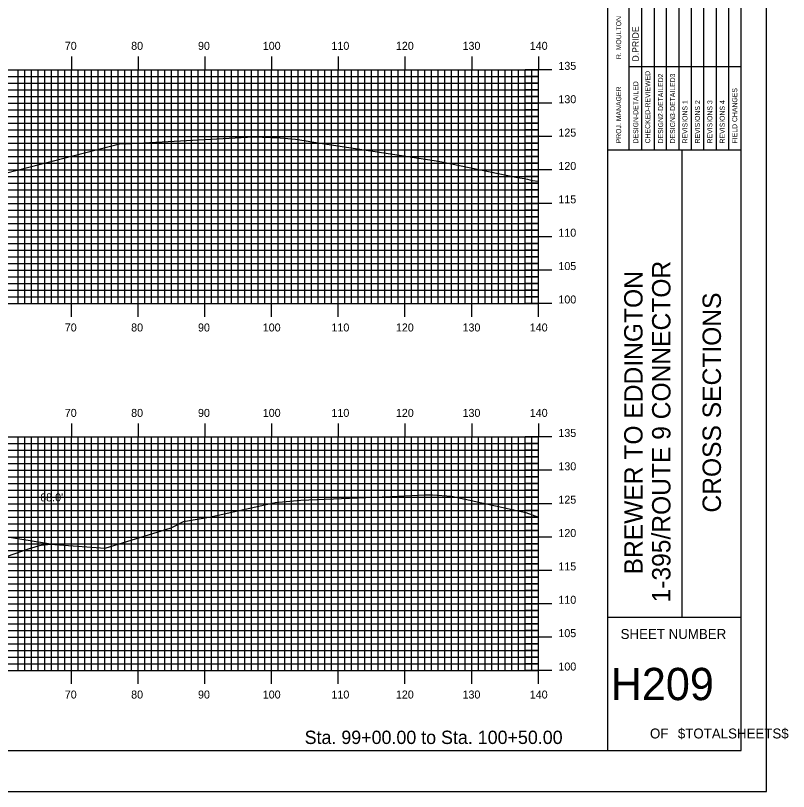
# Model space of a CAD drawing. Extents: x 1766513 to 1766856, y 442591 to 442811.
# Drawn here: x 1766740.5 to 1766856.4, y 442590.5 to 442706.8 of the extents above; entities that cross this region are included whole.
import ezdxf

# ---------------------------------------------------------------- set-up
doc = ezdxf.new("R2010")
doc.units = 0
for name, color, linetype in [('BORDER', 7, 'Continuous'), ('D_Roadway_Centerline', 7, 'Continuous'), ('D_Text_Standard', 7, 'Continuous'), ('H_V ANNOTATION', 7, 'Continuous'), ('MAJOR', 7, 'Continuous'), ('MINOR', 7, 'Continuous'), ('PLOT BOUNDARY', 7, 'Continuous'), ('S_Roadway_Centerline', 7, 'Continuous')]:
    doc.layers.add(name, color=color, linetype=linetype)

msp = doc.modelspace()

# ---------------------------------------------------------------- linework, layer by layer
at = {"layer": 'BORDER'}
for p, q in [((1766829.31, 442596.67), (1766829.31, 442806.67)), ((1766829.31, 442686.67), (1766849.31, 442686.67)), ((1766840.49, 442616.67), (1766840.49, 442686.67)), ((1766829.31, 442616.67), (1766849.31, 442616.67))]:
    msp.add_line(p, q, dxfattribs=at)
msp.add_lwpolyline([(1766529.31, 442596.67), (1766849.31, 442596.67), (1766849.31, 442806.67), (1766529.31, 442806.67)], close=True, dxfattribs=at)
for points in [[(1766834.41, 442686.68), (1766834.41, 442721.67)], [(1766836.27, 442721.67), (1766836.27, 442686.68)], [(1766838.13, 442686.68), (1766838.13, 442721.67)], [(1766840, 442686.68), (1766840, 442721.67)], [(1766841.86, 442686.68), (1766841.86, 442721.67)], [(1766843.72, 442686.68), (1766843.72, 442721.67)], [(1766845.59, 442686.68), (1766845.59, 442721.67)], [(1766847.45, 442686.68), (1766847.45, 442721.67)], [(1766832.54, 442686.68), (1766832.54, 442720.26)], [(1766832.54, 442699.17), (1766849.31, 442699.17)]]:
    msp.add_lwpolyline(points, dxfattribs=at)
at = {"layer": 'D_Roadway_Centerline'}
msp.add_line((1766713.08, 442617.08), (1766742.93, 442627.03), dxfattribs=at)
msp.add_arc((1766746.1, 442617.54), 10, 85.9694, 108.438, dxfattribs=at)
at = {"layer": 'MAJOR'}
for p, q in [((1766748.91, 442700.67), (1766748.91, 442698.67)), ((1766758.91, 442700.67), (1766758.91, 442698.67)), ((1766768.91, 442700.67), (1766768.91, 442698.67)), ((1766778.91, 442700.67), (1766778.91, 442698.67)), ((1766788.91, 442700.67), (1766788.91, 442698.67)), ((1766798.91, 442700.67), (1766798.91, 442698.67)), ((1766808.91, 442700.67), (1766808.91, 442698.67)), ((1766818.91, 442700.67), (1766818.91, 442698.67)), ((1766538.91, 442698.67), (1766818.91, 442698.67)), ((1766538.91, 442698.67), (1766818.91, 442698.67)), ((1766748.91, 442663.67), (1766748.91, 442698.67)), ((1766758.91, 442663.67), (1766758.91, 442698.67)), ((1766768.91, 442663.67), (1766768.91, 442698.67)), ((1766778.91, 442663.67), (1766778.91, 442698.67)), ((1766788.91, 442663.67), (1766788.91, 442698.67)), ((1766798.91, 442663.67), (1766798.91, 442698.67)), ((1766808.91, 442663.67), (1766808.91, 442698.67)), ((1766820.91, 442698.67), (1766816.91, 442698.67)), ((1766818.91, 442663.67), (1766818.91, 442698.67)), ((1766818.91, 442663.67), (1766818.91, 442698.67)), ((1766538.91, 442693.67), (1766818.91, 442693.67)), ((1766820.91, 442693.67), (1766816.91, 442693.67)), ((1766538.91, 442688.67), (1766818.91, 442688.67)), ((1766820.91, 442688.67), (1766816.91, 442688.67)), ((1766538.91, 442683.67), (1766818.91, 442683.67)), ((1766820.91, 442683.67), (1766816.91, 442683.67)), ((1766538.91, 442678.67), (1766818.91, 442678.67)), ((1766820.91, 442678.67), (1766816.91, 442678.67)), ((1766538.91, 442673.67), (1766818.91, 442673.67)), ((1766820.91, 442673.67), (1766816.91, 442673.67)), ((1766538.91, 442668.67), (1766818.91, 442668.67)), ((1766820.91, 442668.67), (1766816.91, 442668.67)), ((1766538.91, 442663.67), (1766818.91, 442663.67)), ((1766538.91, 442663.67), (1766818.91, 442663.67)), ((1766748.91, 442661.66), (1766748.91, 442663.67)), ((1766758.91, 442661.66), (1766758.91, 442663.67)), ((1766768.91, 442661.66), (1766768.91, 442663.67)), ((1766778.91, 442661.66), (1766778.91, 442663.67)), ((1766788.91, 442661.66), (1766788.91, 442663.67)), ((1766798.91, 442661.66), (1766798.91, 442663.67)), ((1766808.91, 442661.66), (1766808.91, 442663.67)), ((1766820.91, 442663.67), (1766816.91, 442663.67)), ((1766818.91, 442661.66), (1766818.91, 442663.67)), ((1766748.91, 442645.67), (1766748.91, 442643.67)), ((1766758.91, 442645.67), (1766758.91, 442643.67)), ((1766768.91, 442645.67), (1766768.91, 442643.67)), ((1766778.91, 442645.67), (1766778.91, 442643.67)), ((1766788.91, 442645.67), (1766788.91, 442643.67)), ((1766798.91, 442645.67), (1766798.91, 442643.67)), ((1766808.91, 442645.67), (1766808.91, 442643.67)), ((1766818.91, 442645.67), (1766818.91, 442643.67)), ((1766538.91, 442643.67), (1766818.91, 442643.67)), ((1766538.91, 442643.67), (1766818.91, 442643.67)), ((1766748.91, 442608.67), (1766748.91, 442643.67)), ((1766758.91, 442608.67), (1766758.91, 442643.67)), ((1766768.91, 442608.67), (1766768.91, 442643.67)), ((1766778.91, 442608.67), (1766778.91, 442643.67)), ((1766788.91, 442608.67), (1766788.91, 442643.67)), ((1766798.91, 442608.67), (1766798.91, 442643.67)), ((1766808.91, 442608.67), (1766808.91, 442643.67)), ((1766820.91, 442643.67), (1766816.91, 442643.67)), ((1766818.91, 442608.67), (1766818.91, 442643.67)), ((1766818.91, 442608.67), (1766818.91, 442643.67)), ((1766538.91, 442638.67), (1766818.91, 442638.67)), ((1766820.91, 442638.67), (1766816.91, 442638.67)), ((1766538.91, 442633.67), (1766818.91, 442633.67)), ((1766820.91, 442633.67), (1766816.91, 442633.67)), ((1766538.91, 442628.67), (1766818.91, 442628.67)), ((1766820.91, 442628.67), (1766816.91, 442628.67)), ((1766538.91, 442623.67), (1766818.91, 442623.67)), ((1766820.91, 442623.67), (1766816.91, 442623.67)), ((1766538.91, 442618.67), (1766818.91, 442618.67)), ((1766820.91, 442618.67), (1766816.91, 442618.67)), ((1766538.91, 442613.67), (1766818.91, 442613.67)), ((1766820.91, 442613.67), (1766816.91, 442613.67)), ((1766538.91, 442608.67), (1766818.91, 442608.67)), ((1766538.91, 442608.67), (1766818.91, 442608.67)), ((1766748.91, 442606.66), (1766748.91, 442608.67)), ((1766758.91, 442606.66), (1766758.91, 442608.67)), ((1766768.91, 442606.66), (1766768.91, 442608.67)), ((1766778.91, 442606.66), (1766778.91, 442608.67)), ((1766788.91, 442606.66), (1766788.91, 442608.67)), ((1766798.91, 442606.66), (1766798.91, 442608.67)), ((1766808.91, 442606.66), (1766808.91, 442608.67)), ((1766820.91, 442608.67), (1766816.91, 442608.67)), ((1766818.91, 442606.66), (1766818.91, 442608.67))]:
    msp.add_line(p, q, dxfattribs=at)
at = {"layer": 'MINOR'}
for p, q in [((1766740.91, 442663.67), (1766740.91, 442698.67)), ((1766741.91, 442663.67), (1766741.91, 442698.67)), ((1766742.91, 442663.67), (1766742.91, 442698.67)), ((1766743.91, 442663.67), (1766743.91, 442698.67)), ((1766744.91, 442663.67), (1766744.91, 442698.67)), ((1766745.91, 442663.67), (1766745.91, 442698.67)), ((1766746.91, 442663.67), (1766746.91, 442698.67)), ((1766747.91, 442663.67), (1766747.91, 442698.67)), ((1766749.91, 442663.67), (1766749.91, 442698.67)), ((1766750.91, 442663.67), (1766750.91, 442698.67)), ((1766751.91, 442663.67), (1766751.91, 442698.67)), ((1766752.91, 442663.67), (1766752.91, 442698.67)), ((1766753.91, 442663.67), (1766753.91, 442698.67)), ((1766754.91, 442663.67), (1766754.91, 442698.67)), ((1766755.91, 442663.67), (1766755.91, 442698.67)), ((1766756.91, 442663.67), (1766756.91, 442698.67)), ((1766757.91, 442663.67), (1766757.91, 442698.67)), ((1766759.91, 442663.67), (1766759.91, 442698.67)), ((1766760.91, 442663.67), (1766760.91, 442698.67)), ((1766761.91, 442663.67), (1766761.91, 442698.67)), ((1766762.91, 442663.67), (1766762.91, 442698.67)), ((1766763.91, 442663.67), (1766763.91, 442698.67)), ((1766764.91, 442663.67), (1766764.91, 442698.67)), ((1766765.91, 442663.67), (1766765.91, 442698.67)), ((1766766.91, 442663.67), (1766766.91, 442698.67)), ((1766767.91, 442663.67), (1766767.91, 442698.67)), ((1766769.91, 442663.67), (1766769.91, 442698.67)), ((1766770.91, 442663.67), (1766770.91, 442698.67)), ((1766771.91, 442663.67), (1766771.91, 442698.67)), ((1766772.91, 442663.67), (1766772.91, 442698.67)), ((1766773.91, 442663.67), (1766773.91, 442698.67)), ((1766774.91, 442663.67), (1766774.91, 442698.67)), ((1766775.91, 442663.67), (1766775.91, 442698.67)), ((1766776.91, 442663.67), (1766776.91, 442698.67)), ((1766777.91, 442663.67), (1766777.91, 442698.67)), ((1766779.91, 442663.67), (1766779.91, 442698.67)), ((1766780.91, 442663.67), (1766780.91, 442698.67)), ((1766781.91, 442663.67), (1766781.91, 442698.67)), ((1766782.91, 442663.67), (1766782.91, 442698.67)), ((1766783.91, 442663.67), (1766783.91, 442698.67)), ((1766784.91, 442663.67), (1766784.91, 442698.67)), ((1766785.91, 442663.67), (1766785.91, 442698.67)), ((1766786.91, 442663.67), (1766786.91, 442698.67)), ((1766787.91, 442663.67), (1766787.91, 442698.67)), ((1766789.91, 442663.67), (1766789.91, 442698.67)), ((1766790.91, 442663.67), (1766790.91, 442698.67)), ((1766791.91, 442663.67), (1766791.91, 442698.67)), ((1766792.91, 442663.67), (1766792.91, 442698.67)), ((1766793.91, 442663.67), (1766793.91, 442698.67)), ((1766794.91, 442663.67), (1766794.91, 442698.67)), ((1766795.91, 442663.67), (1766795.91, 442698.67)), ((1766796.91, 442663.67), (1766796.91, 442698.67)), ((1766797.91, 442663.67), (1766797.91, 442698.67)), ((1766799.91, 442663.67), (1766799.91, 442698.67)), ((1766800.91, 442663.67), (1766800.91, 442698.67)), ((1766801.91, 442663.67), (1766801.91, 442698.67)), ((1766802.91, 442663.67), (1766802.91, 442698.67)), ((1766803.91, 442663.67), (1766803.91, 442698.67)), ((1766804.91, 442663.67), (1766804.91, 442698.67)), ((1766805.91, 442663.67), (1766805.91, 442698.67)), ((1766806.91, 442663.67), (1766806.91, 442698.67)), ((1766807.91, 442663.67), (1766807.91, 442698.67)), ((1766809.91, 442663.67), (1766809.91, 442698.67)), ((1766810.91, 442663.67), (1766810.91, 442698.67)), ((1766811.91, 442663.67), (1766811.91, 442698.67)), ((1766812.91, 442663.67), (1766812.91, 442698.67)), ((1766813.91, 442663.67), (1766813.91, 442698.67)), ((1766814.91, 442663.67), (1766814.91, 442698.67)), ((1766815.91, 442663.67), (1766815.91, 442698.67)), ((1766816.91, 442663.67), (1766816.91, 442698.67)), ((1766817.91, 442663.67), (1766817.91, 442698.67)), ((1766538.91, 442697.67), (1766818.91, 442697.67)), ((1766818.91, 442697.67), (1766816.91, 442697.67)), ((1766538.91, 442696.67), (1766818.91, 442696.67)), ((1766818.91, 442696.67), (1766816.91, 442696.67)), ((1766538.91, 442695.67), (1766818.91, 442695.67)), ((1766818.91, 442695.67), (1766816.91, 442695.67)), ((1766538.91, 442694.67), (1766818.91, 442694.67)), ((1766818.91, 442694.67), (1766816.91, 442694.67)), ((1766538.91, 442692.67), (1766818.91, 442692.67)), ((1766538.91, 442691.67), (1766818.91, 442691.67)), ((1766818.91, 442692.67), (1766816.91, 442692.67)), ((1766818.91, 442691.67), (1766816.91, 442691.67)), ((1766538.91, 442690.67), (1766818.91, 442690.67)), ((1766818.91, 442690.67), (1766816.91, 442690.67)), ((1766538.91, 442689.67), (1766818.91, 442689.67)), ((1766818.91, 442689.67), (1766816.91, 442689.67)), ((1766538.91, 442687.67), (1766818.91, 442687.67)), ((1766818.91, 442687.67), (1766816.91, 442687.67)), ((1766538.91, 442686.67), (1766818.91, 442686.67)), ((1766818.91, 442686.67), (1766816.91, 442686.67)), ((1766538.91, 442685.67), (1766818.91, 442685.67)), ((1766538.91, 442684.67), (1766818.91, 442684.67)), ((1766818.91, 442685.67), (1766816.91, 442685.67)), ((1766818.91, 442684.67), (1766816.91, 442684.67)), ((1766538.91, 442682.67), (1766818.91, 442682.67)), ((1766818.91, 442682.67), (1766816.91, 442682.67)), ((1766538.91, 442681.67), (1766818.91, 442681.67)), ((1766818.91, 442681.67), (1766816.91, 442681.67)), ((1766538.91, 442680.67), (1766818.91, 442680.67)), ((1766818.91, 442680.67), (1766816.91, 442680.67)), ((1766538.91, 442679.67), (1766818.91, 442679.67)), ((1766818.91, 442679.67), (1766816.91, 442679.67)), ((1766538.91, 442677.67), (1766818.91, 442677.67)), ((1766538.91, 442676.67), (1766818.91, 442676.67)), ((1766818.91, 442677.67), (1766816.91, 442677.67)), ((1766818.91, 442676.67), (1766816.91, 442676.67)), ((1766538.91, 442675.67), (1766818.91, 442675.67)), ((1766818.91, 442675.67), (1766816.91, 442675.67)), ((1766538.91, 442674.67), (1766818.91, 442674.67)), ((1766818.91, 442674.67), (1766816.91, 442674.67)), ((1766538.91, 442672.67), (1766818.91, 442672.67)), ((1766818.91, 442672.67), (1766816.91, 442672.67)), ((1766538.91, 442671.67), (1766818.91, 442671.67)), ((1766818.91, 442671.67), (1766816.91, 442671.67)), ((1766538.91, 442670.67), (1766818.91, 442670.67)), ((1766538.91, 442669.67), (1766818.91, 442669.67)), ((1766818.91, 442670.67), (1766816.91, 442670.67)), ((1766818.91, 442669.67), (1766816.91, 442669.67)), ((1766538.91, 442667.67), (1766818.91, 442667.67)), ((1766818.91, 442667.67), (1766816.91, 442667.67)), ((1766538.91, 442666.67), (1766818.91, 442666.67)), ((1766818.91, 442666.67), (1766816.91, 442666.67)), ((1766538.91, 442665.67), (1766818.91, 442665.67)), ((1766818.91, 442665.67), (1766816.91, 442665.67)), ((1766538.91, 442664.67), (1766818.91, 442664.67)), ((1766818.91, 442664.67), (1766816.91, 442664.67)), ((1766740.91, 442608.67), (1766740.91, 442643.67)), ((1766741.91, 442608.67), (1766741.91, 442643.67)), ((1766742.91, 442608.67), (1766742.91, 442643.67)), ((1766743.91, 442608.67), (1766743.91, 442643.67)), ((1766744.91, 442608.67), (1766744.91, 442643.67)), ((1766745.91, 442608.67), (1766745.91, 442643.67)), ((1766746.91, 442608.67), (1766746.91, 442643.67)), ((1766747.91, 442608.67), (1766747.91, 442643.67)), ((1766749.91, 442608.67), (1766749.91, 442643.67)), ((1766750.91, 442608.67), (1766750.91, 442643.67)), ((1766751.91, 442608.67), (1766751.91, 442643.67)), ((1766752.91, 442608.67), (1766752.91, 442643.67)), ((1766753.91, 442608.67), (1766753.91, 442643.67)), ((1766754.91, 442608.67), (1766754.91, 442643.67)), ((1766755.91, 442608.67), (1766755.91, 442643.67)), ((1766756.91, 442608.67), (1766756.91, 442643.67)), ((1766757.91, 442608.67), (1766757.91, 442643.67)), ((1766759.91, 442608.67), (1766759.91, 442643.67)), ((1766760.91, 442608.67), (1766760.91, 442643.67)), ((1766761.91, 442608.67), (1766761.91, 442643.67)), ((1766762.91, 442608.67), (1766762.91, 442643.67)), ((1766763.91, 442608.67), (1766763.91, 442643.67)), ((1766764.91, 442608.67), (1766764.91, 442643.67)), ((1766765.91, 442608.67), (1766765.91, 442643.67)), ((1766766.91, 442608.67), (1766766.91, 442643.67)), ((1766767.91, 442608.67), (1766767.91, 442643.67)), ((1766769.91, 442608.67), (1766769.91, 442643.67)), ((1766770.91, 442608.67), (1766770.91, 442643.67)), ((1766771.91, 442608.67), (1766771.91, 442643.67)), ((1766772.91, 442608.67), (1766772.91, 442643.67)), ((1766773.91, 442608.67), (1766773.91, 442643.67)), ((1766774.91, 442608.67), (1766774.91, 442643.67)), ((1766775.91, 442608.67), (1766775.91, 442643.67)), ((1766776.91, 442608.67), (1766776.91, 442643.67)), ((1766777.91, 442608.67), (1766777.91, 442643.67)), ((1766779.91, 442608.67), (1766779.91, 442643.67)), ((1766780.91, 442608.67), (1766780.91, 442643.67)), ((1766781.91, 442608.67), (1766781.91, 442643.67)), ((1766782.91, 442608.67), (1766782.91, 442643.67)), ((1766783.91, 442608.67), (1766783.91, 442643.67)), ((1766784.91, 442608.67), (1766784.91, 442643.67)), ((1766785.91, 442608.67), (1766785.91, 442643.67)), ((1766786.91, 442608.67), (1766786.91, 442643.67)), ((1766787.91, 442608.67), (1766787.91, 442643.67)), ((1766789.91, 442608.67), (1766789.91, 442643.67)), ((1766790.91, 442608.67), (1766790.91, 442643.67)), ((1766791.91, 442608.67), (1766791.91, 442643.67)), ((1766792.91, 442608.67), (1766792.91, 442643.67)), ((1766793.91, 442608.67), (1766793.91, 442643.67)), ((1766794.91, 442608.67), (1766794.91, 442643.67)), ((1766795.91, 442608.67), (1766795.91, 442643.67)), ((1766796.91, 442608.67), (1766796.91, 442643.67)), ((1766797.91, 442608.67), (1766797.91, 442643.67)), ((1766799.91, 442608.67), (1766799.91, 442643.67)), ((1766800.91, 442608.67), (1766800.91, 442643.67)), ((1766801.91, 442608.67), (1766801.91, 442643.67)), ((1766802.91, 442608.67), (1766802.91, 442643.67)), ((1766803.91, 442608.67), (1766803.91, 442643.67)), ((1766804.91, 442608.67), (1766804.91, 442643.67)), ((1766805.91, 442608.67), (1766805.91, 442643.67)), ((1766806.91, 442608.67), (1766806.91, 442643.67)), ((1766807.91, 442608.67), (1766807.91, 442643.67)), ((1766809.91, 442608.67), (1766809.91, 442643.67)), ((1766810.91, 442608.67), (1766810.91, 442643.67)), ((1766811.91, 442608.67), (1766811.91, 442643.67)), ((1766812.91, 442608.67), (1766812.91, 442643.67)), ((1766813.91, 442608.67), (1766813.91, 442643.67)), ((1766814.91, 442608.67), (1766814.91, 442643.67)), ((1766815.91, 442608.67), (1766815.91, 442643.67)), ((1766816.91, 442608.67), (1766816.91, 442643.67)), ((1766817.91, 442608.67), (1766817.91, 442643.67)), ((1766538.91, 442642.67), (1766818.91, 442642.67)), ((1766538.91, 442641.67), (1766818.91, 442641.67)), ((1766818.91, 442642.67), (1766816.91, 442642.67)), ((1766818.91, 442641.67), (1766816.91, 442641.67)), ((1766538.91, 442640.67), (1766818.91, 442640.67)), ((1766818.91, 442640.67), (1766816.91, 442640.67)), ((1766538.91, 442639.67), (1766818.91, 442639.67)), ((1766818.91, 442639.67), (1766816.91, 442639.67)), ((1766538.91, 442637.67), (1766818.91, 442637.67)), ((1766818.91, 442637.67), (1766816.91, 442637.67)), ((1766538.91, 442636.67), (1766818.91, 442636.67)), ((1766818.91, 442636.67), (1766816.91, 442636.67)), ((1766538.91, 442635.67), (1766818.91, 442635.67)), ((1766538.91, 442634.67), (1766818.91, 442634.67)), ((1766818.91, 442635.67), (1766816.91, 442635.67)), ((1766818.91, 442634.67), (1766816.91, 442634.67)), ((1766538.91, 442632.67), (1766818.91, 442632.67)), ((1766818.91, 442632.67), (1766816.91, 442632.67)), ((1766538.91, 442631.67), (1766818.91, 442631.67)), ((1766818.91, 442631.67), (1766816.91, 442631.67)), ((1766538.91, 442630.67), (1766818.91, 442630.67)), ((1766818.91, 442630.67), (1766816.91, 442630.67)), ((1766538.91, 442629.67), (1766818.91, 442629.67)), ((1766818.91, 442629.67), (1766816.91, 442629.67)), ((1766538.91, 442627.67), (1766818.91, 442627.67)), ((1766538.91, 442626.67), (1766818.91, 442626.67)), ((1766818.91, 442627.67), (1766816.91, 442627.67)), ((1766818.91, 442626.67), (1766816.91, 442626.67)), ((1766538.91, 442625.67), (1766818.91, 442625.67)), ((1766818.91, 442625.67), (1766816.91, 442625.67)), ((1766538.91, 442624.67), (1766818.91, 442624.67)), ((1766818.91, 442624.67), (1766816.91, 442624.67)), ((1766538.91, 442622.67), (1766818.91, 442622.67)), ((1766818.91, 442622.67), (1766816.91, 442622.67)), ((1766538.91, 442621.67), (1766818.91, 442621.67)), ((1766818.91, 442621.67), (1766816.91, 442621.67)), ((1766538.91, 442620.67), (1766818.91, 442620.67)), ((1766538.91, 442619.67), (1766818.91, 442619.67)), ((1766818.91, 442620.67), (1766816.91, 442620.67)), ((1766818.91, 442619.67), (1766816.91, 442619.67)), ((1766538.91, 442617.67), (1766818.91, 442617.67)), ((1766818.91, 442617.67), (1766816.91, 442617.67)), ((1766538.91, 442616.67), (1766818.91, 442616.67)), ((1766818.91, 442616.67), (1766816.91, 442616.67)), ((1766538.91, 442615.67), (1766818.91, 442615.67)), ((1766818.91, 442615.67), (1766816.91, 442615.67)), ((1766538.91, 442614.67), (1766818.91, 442614.67)), ((1766818.91, 442614.67), (1766816.91, 442614.67)), ((1766538.91, 442612.67), (1766818.91, 442612.67)), ((1766818.91, 442612.67), (1766816.91, 442612.67)), ((1766538.91, 442611.67), (1766818.91, 442611.67)), ((1766818.91, 442611.67), (1766816.91, 442611.67)), ((1766538.91, 442610.67), (1766818.91, 442610.67)), ((1766818.91, 442610.67), (1766816.91, 442610.67)), ((1766538.91, 442609.67), (1766818.91, 442609.67)), ((1766818.91, 442609.67), (1766816.91, 442609.67))]:
    msp.add_line(p, q, dxfattribs=at)
at = {"layer": 'PLOT BOUNDARY'}
msp.add_lwpolyline([(1766513.12, 442590.55), (1766853.12, 442590.55), (1766853.12, 442810.55), (1766513.12, 442810.55)], close=True, dxfattribs=at)
at = {"layer": 'S_Roadway_Centerline'}
for points in [[(1766725.16, 442679.65), (1766756.32, 442687.64), (1766757, 442687.61), (1766776.18, 442688.63), (1766780.21, 442688.47), (1766782.51, 442688.29), (1766784.08, 442688.04), (1766784.96, 442687.89), (1766785.89, 442687.74), (1766803.28, 442685.11), (1766804.46, 442684.91), (1766815.76, 442682.56), (1766816.12, 442682.5), (1766816.49, 442682.44), (1766816.84, 442682.38), (1766817.26, 442682.3), (1766817.96, 442682.1), (1766818.91, 442681.97)], [(1766738.03, 442628.92), (1766746.42, 442627.55), (1766753.97, 442627.01), (1766763.85, 442630.04), (1766765.71, 442631.01), (1766769.82, 442631.72), (1766779.44, 442633.86), (1766783.32, 442634.2), (1766797.92, 442634.81), (1766801.86, 442634.99), (1766803.03, 442635), (1766805.87, 442634.77), (1766817.05, 442632.36), (1766818.91, 442631.66)]]:
    msp.add_lwpolyline(points, dxfattribs=at)

# ---------------------------------------------------------------- texts
at = {"layer": 'BORDER'}
for s, height, p in [('R. MOULTON', 0.745, (1766831.32, 442700.28)), ('D.PRIDE', 0.969, (1766833.96, 442699.92)), ('CHECKED-REVIEWED', 0.7455, (1766835.67, 442687.65)), ('DESIGN2-DETAILED2', 0.7455, (1766837.61, 442687.65)), ('DESIGN3-DETAILED3', 0.7455, (1766839.4, 442687.65)), ('DESIGN-DETAILED', 0.7455, (1766833.88, 442687.65)), ('PROJ. MANAGER', 0.7455, (1766831.32, 442687.65)), ('FIELD CHANGES', 0.7455, (1766848.72, 442687.65)), ('REVISIONS 1', 0.7455, (1766841.26, 442687.65)), ('REVISIONS 2', 0.7455, (1766843.13, 442687.65)), ('REVISIONS 3', 0.7455, (1766844.99, 442687.65)), ('REVISIONS 4', 0.7455, (1766846.85, 442687.65)), ('1-395/ROUTE 9 CONNECTOR', 2.7557, (1766838.71, 442618.87)), ('BREWER TO EDDINGTON', 2.7557, (1766834.53, 442623.07)), ('CROSS SECTIONS', 2.7557, (1766846.28, 442632.34))]:
    msp.add_text(s, height=height, rotation=90, dxfattribs=at).set_placement(p)
for s, height, p in [('SHEET NUMBER', 1.4905, (1766831.24, 442613.4)), ('H209', 4.839, (1766829.75, 442604.23)), ('OF', 1.491, (1766835.64, 442598.49)), ('$TOTALSHEETS$', 1.4905, (1766839.82, 442598.49))]:
    msp.add_text(s, height=height, dxfattribs=at).set_placement(p)
at = {"layer": 'D_Text_Standard'}
msp.add_text("68.0'", height=1.2, dxfattribs=at).set_placement((1766744.23, 442634.01))
at = {"layer": 'H_V ANNOTATION'}
for s, height, p in [('70', 1.2, (1766747.91, 442701.67)), ('80', 1.2, (1766757.86, 442701.67)), ('90', 1.2, (1766767.88, 442701.67)), ('100', 1.2, (1766777.59, 442701.67)), ('110', 1.2, (1766787.89, 442701.67)), ('120', 1.2, (1766797.55, 442701.67)), ('130', 1.2, (1766807.54, 442701.67)), ('140', 1.2, (1766817.62, 442701.67)), ('135', 1.2, (1766821.91, 442698.67)), ('130', 1.2, (1766821.91, 442693.67)), ('125', 1.2, (1766821.91, 442688.67)), ('120', 1.2, (1766821.91, 442683.67)), ('115', 1.2, (1766821.91, 442678.67)), ('110', 1.2, (1766821.91, 442673.67)), ('105', 1.2, (1766821.91, 442668.67)), ('100', 1.2, (1766821.91, 442663.67)), ('70', 1.2, (1766747.91, 442659.47)), ('80', 1.2, (1766757.86, 442659.47)), ('90', 1.2, (1766767.88, 442659.47)), ('100', 1.2, (1766777.59, 442659.47)), ('110', 1.2, (1766787.89, 442659.47)), ('120', 1.2, (1766797.55, 442659.47)), ('130', 1.2, (1766807.54, 442659.47)), ('140', 1.2, (1766817.62, 442659.47)), ('70', 1.2, (1766747.91, 442646.67)), ('80', 1.2, (1766757.86, 442646.67)), ('90', 1.2, (1766767.88, 442646.67)), ('100', 1.2, (1766777.59, 442646.67)), ('110', 1.2, (1766787.89, 442646.67)), ('120', 1.2, (1766797.55, 442646.67)), ('130', 1.2, (1766807.54, 442646.67)), ('140', 1.2, (1766817.62, 442646.67)), ('135', 1.2, (1766821.91, 442643.67)), ('130', 1.2, (1766821.91, 442638.67)), ('125', 1.2, (1766821.91, 442633.67)), ('120', 1.2, (1766821.91, 442628.67)), ('115', 1.2, (1766821.91, 442623.67)), ('110', 1.2, (1766821.91, 442618.67)), ('105', 1.2, (1766821.91, 442613.67)), ('100', 1.2, (1766821.91, 442608.67)), ('70', 1.2, (1766747.91, 442604.47)), ('80', 1.2, (1766757.86, 442604.47)), ('90', 1.2, (1766767.88, 442604.47)), ('100', 1.2, (1766777.59, 442604.47)), ('110', 1.2, (1766787.89, 442604.47)), ('120', 1.2, (1766797.55, 442604.47)), ('130', 1.2, (1766807.54, 442604.47)), ('140', 1.2, (1766817.62, 442604.47)), ('Sta. 99+00.00 to Sta. 100+50.00', 2.0004, (1766783.87, 442597.66))]:
    msp.add_text(s, height=height, dxfattribs=at).set_placement(p)

doc.saveas('drawing.dxf')
